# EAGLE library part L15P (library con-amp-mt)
AMP MT CONNECTOR
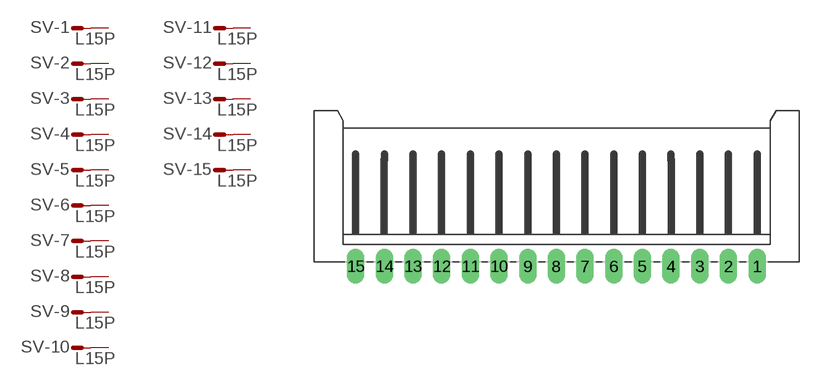
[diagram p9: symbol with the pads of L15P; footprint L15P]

Designator prefix SV; gates -1=M -2=M -3=M -4=M -5=M -6=M -7=M -8=M -9=M -10=M -11=M -12=M -13=M -14=M -15=M

## L15P (OC_FARNELL: unknown; OC_NEWARK: unknown)  [L15P]
1  -1:S  pas
2  -2:S  pas
3  -3:S  pas
4  -4:S  pas
5  -5:S  pas
6  -6:S  pas
7  -7:S  pas
8  -8:S  pas
9  -9:S  pas
10  -10:S  pas
11  -11:S  pas
12  -12:S  pas
13  -13:S  pas
14  -14:S  pas
15  -15:S  pas

## Footprint L15P (pad centres in mm)
AMP MT CONNECTOR
drill 1.016 long: 1 17.5,-6.25; 2 15,-6.25; 3 12.5,-6.25; 4 10,-6.25; 5 7.5,-6.25; 6 5,-6.25; 7 2.5,-6.25; 8 0,-6.25; 9 -2.5,-6.25; 10 -5,-6.25; 11 -7.5,-6.25; 12 -10,-6.25; 13 -12.5,-6.25; 14 -15,-6.25; 15 -17.5,-6.25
